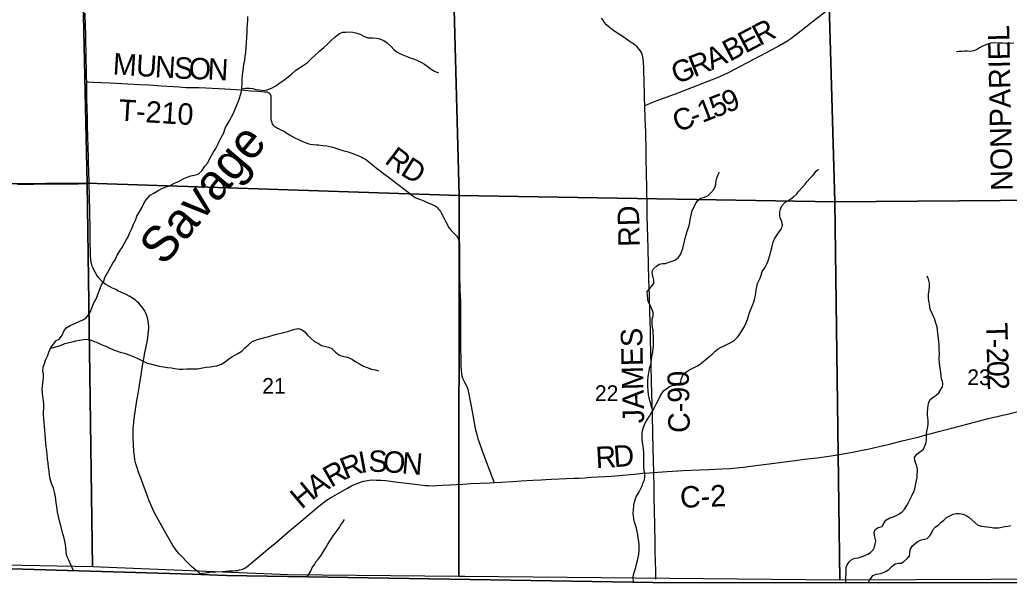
# Model space of a CAD drawing. Extents: x 1985906 to 2360102, y 891258 to 1222054.
# Drawn here: x 2119481 to 2133334, y 971932 to 979818 of the extents above; entities that cross this region are included whole.
import ezdxf

# ---------------------------------------------------------------- set-up
doc = ezdxf.new("R2010")
doc.units = 0
for name, color, linetype in [('GM_X_Adjacent_County', 7, 'Continuous'), ('GM_X_County', 7, 'Continuous'), ('GM_X_County_Road', 7, 'Continuous'), ('GM_X_County_Road_Text', 7, 'Continuous'), ('GM_X_Minor_River', 7, 'Continuous'), ('GM_X_Minor_River_Text', 7, 'Continuous'), ('GM_X_Section', 7, 'Continuous'), ('GM_X_Section_Text', 7, 'Continuous'), ('GM_X_State_Route', 7, 'Continuous'), ('GM_X_Township', 7, 'Continuous'), ('GM_X_Township_Road', 7, 'Continuous'), ('GM_X_Township_Road_Text', 7, 'Continuous')]:
    doc.layers.add(name, color=color, linetype=linetype)

msp = doc.modelspace()

# ---------------------------------------------------------------- linework, layer by layer
at = {"layer": 'GM_X_Adjacent_County'}
msp.add_lwpolyline([(2092530, 972203), (2095843, 972202), (2097718, 972193), (2100221, 972181), (2101119, 972173), (2101924, 972165), (2105883, 972151), (2108565, 972150), (2109260, 972143), (2113052, 972101), (2115190, 972104), (2119200, 972136), (2121896, 972057), (2122376, 972042), (2128345, 971944), (2133617, 971935)], dxfattribs=at)
at = {"layer": 'GM_X_County'}
msp.add_lwpolyline([(2133617, 971935), (2128345, 971944), (2122376, 972042), (2121896, 972057), (2119200, 972136), (2115190, 972104), (2113052, 972101), (2109260, 972143), (2108565, 972150), (2105883, 972151), (2101924, 972165), (2101119, 972173), (2100221, 972181), (2097718, 972193), (2095843, 972202), (2092530, 972203)], dxfattribs=at)
at = {"layer": 'GM_X_County_Road'}
for points in [[(2128232, 978618), (2128268, 978633), (2128313, 978652), (2128405, 978688), (2128697, 978797), (2129080, 978944), (2129248, 979011), (2129323, 979044), (2129412, 979087), (2129573, 979169), (2129660, 979215), (2130022, 979408), (2130109, 979454), (2130166, 979486), (2130222, 979521), (2130276, 979558), (2130355, 979618), (2130484, 979719), (2130639, 979841), (2130757, 979929), (2130784, 979947), (2130812, 979962), (2130827, 979968)], [(2128232, 978618), (2128229, 978712), (2128227, 978794), (2128221, 978926), (2128216, 979138), (2128212, 979236), (2128209, 979268), (2128204, 979300), (2128196, 979331), (2128190, 979346), (2128184, 979361), (2128176, 979375), (2128168, 979388), (2128149, 979414), (2128127, 979438), (2128102, 979459), (2128076, 979478), (2128056, 979493), (2128028, 979512), (2127994, 979535), (2127914, 979589), (2127842, 979636), (2127781, 979676), (2127733, 979714), (2127697, 979748), (2127662, 979787), (2127642, 979816), (2127626, 979840)], [(2128310, 975476), (2128301, 975726), (2128296, 975956), (2128293, 976071), (2128289, 976174), (2128282, 976389), (2128278, 976616), (2128275, 976776), (2128267, 977071), (2128264, 977203), (2128259, 977456), (2128255, 977680), (2128253, 977859), (2128250, 978055), (2128247, 978155), (2128245, 978252), (2128238, 978433), (2128232, 978614), (2128232, 978618)], [(2128358, 973483), (2128355, 973640), (2128344, 974017), (2128338, 974295), (2128331, 974590), (2128326, 974755), (2128321, 974978), (2128313, 975343), (2128310, 975476)], [(2128358, 973483), (2128412, 973487), (2128543, 973495), (2128771, 973509), (2128999, 973521), (2129130, 973525), (2129310, 973531), (2129424, 973538), (2129522, 973547), (2129652, 973562), (2129750, 973574), (2130010, 973608), (2130157, 973626), (2130335, 973651), (2130465, 973668), (2130645, 973689), (2130775, 973705), (2130840, 973715), (2130953, 973734), (2131066, 973753), (2131163, 973771), (2131275, 973792), (2131355, 973809), (2131515, 973846), (2131659, 973880), (2131834, 973923), (2131977, 973958), (2132072, 973982), (2132199, 974016), (2132262, 974033), (2132342, 974054), (2132532, 974104), (2132738, 974158), (2132865, 974191), (2133039, 974236), (2133182, 974271), (2133326, 974305), (2133533, 974352)], [(2126118, 973342), (2126222, 973347), (2126386, 973357), (2126501, 973364), (2126665, 973373), (2126779, 973379), (2126845, 973383), (2126926, 973387), (2127135, 973397), (2127243, 973402), (2127309, 973402), (2127391, 973408), (2127481, 973414), (2127677, 973426), (2127759, 973432), (2127873, 973441), (2128085, 973459), (2128199, 973470), (2128297, 973478), (2128358, 973483)], [(2128387, 971990), (2128385, 972085), (2128382, 972248), (2128379, 972363), (2128376, 972543), (2128373, 972691), (2128371, 972789), (2128368, 972903), (2128367, 972952), (2128364, 973116), (2128362, 973280), (2128358, 973476), (2128358, 973483)], [(2122004, 972070), (2122078, 972079), (2122142, 972085), (2122227, 972092), (2122315, 972097), (2122408, 972103), (2122471, 972106), (2122508, 972109), (2122533, 972112), (2122557, 972117), (2122599, 972129), (2122630, 972143), (2122665, 972165), (2122712, 972203), (2122749, 972234), (2122861, 972329), (2122982, 972430), (2123047, 972484), (2123258, 972664), (2123422, 972802), (2123670, 973011), (2123724, 973054), (2123774, 973092), (2123830, 973128), (2123929, 973184), (2124071, 973264), (2124126, 973294), (2124177, 973317), (2124218, 973334), (2124251, 973346), (2124291, 973358), (2124328, 973367), (2124374, 973374), (2124424, 973377), (2124476, 973376), (2124542, 973374), (2124607, 973369), (2124769, 973348), (2124901, 973332), (2125015, 973318), (2125155, 973301), (2125205, 973298), (2125259, 973297), (2125321, 973299), (2125393, 973303), (2125495, 973308), (2125684, 973319), (2125798, 973326), (2125927, 973332), (2126060, 973339), (2126118, 973342)]]:
    msp.add_lwpolyline(points, dxfattribs=at)
at = {"layer": 'GM_X_Minor_River'}
for points in [[(2121575, 977496), (2121655, 977536), (2121701, 977554), (2121780, 977596), (2121826, 977614), (2121878, 977634), (2121924, 977644), (2121980, 977656), (2122028, 977706), (2122070, 977770), (2122112, 977816), (2122138, 977868), (2122190, 977961), (2122228, 978019), (2122250, 978063), (2122272, 978115), (2122299, 978169), (2122337, 978237), (2122357, 978301), (2122387, 978358), (2122417, 978402), (2122443, 978458), (2122475, 978512), (2122493, 978558), (2122513, 978616), (2122539, 978670), (2122559, 978720), (2122573, 978767), (2122584, 978815), (2122592, 978867), (2122594, 978931), (2122596, 978989), (2122598, 979035), (2122604, 979086), (2122612, 979136), (2122620, 979200), (2122630, 979248), (2122638, 979308), (2122644, 979356), (2122652, 979437), (2122653, 979499), (2122659, 979573), (2122663, 979635), (2122665, 979707), (2122669, 979754), (2122673, 979808), (2122673, 979864)], [(2122590, 978853), (2122642, 978861), (2122696, 978861), (2122744, 978855), (2122788, 978844), (2122840, 978836), (2122884, 978830), (2122944, 978838), (2123006, 978862), (2123064, 978894), (2123124, 978934), (2123180, 978974), (2123238, 979018), (2123292, 979064), (2123342, 979108), (2123388, 979140), (2123448, 979178), (2123508, 979220), (2123565, 979275), (2123613, 979319), (2123681, 979383), (2123739, 979431), (2123791, 979477), (2123847, 979533), (2123895, 979579), (2123959, 979625), (2124003, 979645), (2124047, 979647), (2124095, 979651), (2124145, 979647), (2124201, 979629), (2124247, 979615), (2124299, 979588), (2124353, 979568), (2124421, 979564), (2124473, 979560), (2124519, 979550), (2124577, 979530), (2124625, 979498), (2124679, 979445), (2124719, 979401), (2124765, 979363), (2124821, 979335), (2124867, 979317), (2124913, 979300), (2124961, 979280), (2125005, 979268), (2125051, 979250), (2125097, 979226), (2125147, 979196), (2125197, 979161), (2125241, 979125), (2125285, 979097), (2125343, 979077)], [(2133400, 979489), (2133330, 979487), (2133288, 979485), (2133246, 979489), (2133198, 979493), (2133114, 979494), (2133074, 979492), (2133020, 979472), (2132958, 979450), (2132918, 979426), (2132874, 979400), (2132832, 979384), (2132790, 979374), (2132746, 979378), (2132710, 979380), (2132672, 979376), (2132634, 979374), (2132594, 979370)], [(2129808, 976126), (2129846, 976202), (2129862, 976242), (2129877, 976296), (2129913, 976348), (2129941, 976403), (2129959, 976443), (2129975, 976489), (2129987, 976539), (2129997, 976575), (2130009, 976625), (2130019, 976667), (2130031, 976707), (2130049, 976752), (2130085, 976808), (2130115, 976852), (2130147, 976892), (2130160, 976948), (2130148, 976994), (2130126, 977044), (2130124, 977083), (2130122, 977129), (2130130, 977169), (2130150, 977215), (2130192, 977259), (2130232, 977285), (2130274, 977311), (2130318, 977343), (2130358, 977383), (2130390, 977419), (2130436, 977471), (2130476, 977517), (2130503, 977557), (2130543, 977596), (2130583, 977640), (2130629, 977698), (2130665, 977726)], [(2128345, 974354), (2128325, 974399), (2128315, 974445), (2128303, 974487), (2128293, 974531), (2128284, 974571), (2128278, 974628), (2128272, 974686), (2128272, 974772), (2128280, 974816), (2128284, 974856), (2128292, 974896), (2128298, 974941), (2128314, 974989), (2128322, 975025), (2128326, 975063), (2128336, 975129), (2128344, 975171), (2128350, 975213), (2128353, 975251), (2128355, 975294), (2128355, 975380), (2128349, 975434), (2128347, 975476), (2128341, 975514), (2128337, 975552), (2128337, 975589), (2128335, 975631), (2128347, 975675), (2128349, 975719), (2128335, 975759), (2128319, 975797), (2128297, 975839), (2128281, 975876), (2128273, 975912), (2128268, 975960), (2128266, 976014), (2128296, 976054), (2128332, 976092), (2128356, 976132), (2128358, 976172), (2128348, 976211), (2128338, 976253), (2128336, 976293), (2128352, 976333), (2128396, 976369), (2128434, 976399), (2128480, 976405), (2128520, 976409), (2128566, 976425), (2128602, 976435), (2128652, 976453), (2128700, 976487), (2128730, 976533), (2128751, 976579), (2128763, 976619), (2128773, 976657), (2128781, 976697), (2128797, 976760), (2128813, 976810), (2128823, 976860), (2128839, 976896), (2128851, 976938), (2128861, 976982), (2128867, 977020), (2128877, 977063), (2128885, 977107), (2128897, 977151), (2128919, 977191), (2128942, 977241), (2128974, 977287), (2129010, 977321), (2129052, 977333), (2129112, 977355), (2129154, 977395), (2129198, 977443), (2129216, 977483), (2129226, 977519), (2129230, 977566), (2129242, 977602), (2129258, 977654), (2129278, 977690)], [(2119985, 973104), (2119977, 973163), (2119965, 973207), (2119951, 973263), (2119925, 973329), (2119905, 973394), (2119899, 973442), (2119893, 973500), (2119885, 973554), (2119877, 973610), (2119869, 973671), (2119863, 973729), (2119860, 973785), (2119852, 973843), (2119846, 973897), (2119842, 973950), (2119838, 974016), (2119832, 974074), (2119828, 974124), (2119822, 974180), (2119814, 974289), (2119812, 974333), (2119816, 974379), (2119818, 974437), (2119813, 974489), (2119805, 974544), (2119797, 974592), (2119795, 974644), (2119799, 974694), (2119807, 974766), (2119811, 974810), (2119811, 974856), (2119803, 974901), (2119807, 974955), (2119825, 975001), (2119843, 975055), (2119867, 975109), (2119890, 975167), (2119918, 975230), (2119956, 975282), (2119988, 975326), (2120036, 975352), (2120076, 975402), (2120100, 975458), (2120132, 975508), (2120188, 975540), (2120260, 975572), (2120314, 975594), (2120366, 975620), (2120410, 975648), (2120452, 975698), (2120475, 975746), (2120493, 975796), (2120515, 975846), (2120551, 975913), (2120571, 975959), (2120601, 976047), (2120627, 976107), (2120657, 976161), (2120673, 976213), (2120709, 976278), (2120739, 976326), (2120782, 976410), (2120816, 976460), (2120844, 976524), (2120880, 976584), (2120914, 976632), (2120946, 976693), (2120974, 976741), (2121002, 976791), (2121020, 976839), (2121050, 976895), (2121078, 976967), (2121107, 977025), (2121121, 977069), (2121149, 977114), (2121195, 977194), (2121223, 977254), (2121249, 977298), (2121305, 977362), (2121359, 977390), (2121427, 977434), (2121471, 977456), (2121529, 977478), (2121575, 977496)], [(2131447, 972435), (2131448, 972437), (2131456, 972483), (2131464, 972521), (2131458, 972562), (2131448, 972600), (2131444, 972642), (2131458, 972684), (2131500, 972710), (2131554, 972726), (2131584, 972778), (2131606, 972814), (2131654, 972842), (2131694, 972856), (2131734, 972868), (2131780, 972892), (2131828, 972926), (2131867, 972970), (2131901, 973020), (2131923, 973062), (2131947, 973109), (2131969, 973155), (2131997, 973215), (2132013, 973253), (2132025, 973329), (2132035, 973371), (2132043, 973413), (2132045, 973449), (2132049, 973498), (2132051, 973534), (2132041, 973572), (2132024, 973608), (2132012, 973648), (2132008, 973690), (2132038, 973736), (2132078, 973766), (2132132, 973808), (2132152, 973853), (2132168, 973889), (2132174, 973927), (2132176, 973973), (2132174, 974027), (2132186, 974081), (2132196, 974123), (2132200, 974162), (2132198, 974206), (2132192, 974250), (2132189, 974290), (2132191, 974328), (2132195, 974376), (2132199, 974422), (2132209, 974460), (2132227, 974505), (2132267, 974535), (2132311, 974565), (2132347, 974597), (2132377, 974645), (2132399, 974681), (2132405, 974717), (2132399, 974755), (2132387, 974791), (2132381, 974831), (2132375, 974880), (2132370, 974920), (2132364, 974968), (2132358, 975014), (2132354, 975084), (2132356, 975146), (2132354, 975203), (2132352, 975273), (2132350, 975309), (2132344, 975363), (2132336, 975425), (2132328, 975478), (2132324, 975520), (2132308, 975570), (2132288, 975638), (2132267, 975674), (2132251, 975723), (2132227, 975763), (2132217, 975841), (2132209, 975879), (2132203, 975929), (2132205, 975981), (2132211, 976030), (2132217, 976090), (2132219, 976134), (2132203, 976188)], [(2132203, 976188), (2132187, 976228)], [(2128086, 973064), (2128095, 973097), (2128113, 973139), (2128138, 973189), (2128164, 973231), (2128182, 973269), (2128198, 973305), (2128210, 973341), (2128226, 973380), (2128232, 973420), (2128232, 973458), (2128222, 973510), (2128216, 973558), (2128216, 973632), (2128218, 973671), (2128218, 973725), (2128216, 973761), (2128214, 973811), (2128208, 973851), (2128201, 973903), (2128197, 973943), (2128193, 974024), (2128201, 974070), (2128217, 974132), (2128235, 974172), (2128271, 974228), (2128299, 974272), (2128321, 974310), (2128343, 974351), (2128371, 974403), (2128395, 974449), (2128423, 974501), (2128440, 974541), (2128470, 974589), (2128498, 974627), (2128536, 974653), (2128576, 974683), (2128620, 974697), (2128660, 974703), (2128696, 974713), (2128738, 974747), (2128742, 974783), (2128754, 974825), (2128780, 974861), (2128822, 974894), (2128858, 974918), (2128912, 974946), (2128968, 974974), (2129006, 974996), (2129044, 975030), (2129091, 975066), (2129129, 975100), (2129177, 975140), (2129213, 975174), (2129259, 975212), (2129299, 975238), (2129335, 975250), (2129381, 975272), (2129437, 975300), (2129479, 975326), (2129529, 975378), (2129561, 975416), (2129591, 975464), (2129621, 975518), (2129647, 975566), (2129670, 975622), (2129686, 975687), (2129706, 975743), (2129726, 975787), (2129744, 975833), (2129760, 975871), (2129774, 975921), (2129782, 975959), (2129786, 975996), (2129790, 976036), (2129798, 976082), (2129808, 976126)], [(2119916, 975224), (2120006, 975247), (2120060, 975265), (2120112, 975287), (2120216, 975311), (2120268, 975325), (2120316, 975335), (2120372, 975345), (2120422, 975347), (2120482, 975335), (2120526, 975315), (2120574, 975295), (2120642, 975264), (2120688, 975248), (2120740, 975222), (2120792, 975200), (2120888, 975168), (2120944, 975154), (2121000, 975131), (2121046, 975115), (2121090, 975095), (2121136, 975075), (2121210, 975039), (2121266, 975013), (2121312, 975002), (2121432, 974972), (2121492, 974960), (2121548, 974952), (2121606, 974948), (2121650, 974938), (2121712, 974930), (2121762, 974927), (2121820, 974933), (2121878, 974933), (2121924, 974931), (2121970, 974931), (2122038, 974945), (2122090, 974955), (2122152, 974961), (2122196, 974969), (2122240, 974975), (2122304, 974997), (2122356, 975029), (2122410, 975071), (2122460, 975107), (2122532, 975149), (2122590, 975181), (2122633, 975227), (2122677, 975265), (2122735, 975313), (2122807, 975341), (2122859, 975355), (2122909, 975373), (2122967, 975387), (2123027, 975405), (2123077, 975419), (2123135, 975431), (2123191, 975445), (2123235, 975457), (2123285, 975473), (2123331, 975487), (2123377, 975497), (2123423, 975482), (2123473, 975450), (2123511, 975406), (2123557, 975362), (2123605, 975316), (2123661, 975287), (2123707, 975259), (2123761, 975245), (2123807, 975237), (2123851, 975215), (2123899, 975167), (2123949, 975130), (2123993, 975112), (2124045, 975102), (2124093, 975086), (2124137, 975064), (2124187, 975032), (2124237, 975004), (2124293, 974969), (2124345, 974951), (2124405, 974927), (2124459, 974919), (2124503, 974905)], [(2120234, 972107), (2120169, 972254), (2120142, 972310), (2120132, 972376), (2120126, 972426), (2120122, 972474), (2120110, 972519), (2120098, 972581), (2120084, 972625), (2120068, 972681), (2120056, 972739), (2120042, 972785), (2120022, 972864), (2120010, 972928), (2119999, 973004), (2119989, 973056), (2119985, 973101), (2119985, 973104)], [(2128072, 971948), (2128068, 972019), (2128078, 972066), (2128090, 972108), (2128104, 972152), (2128114, 972200), (2128128, 972250), (2128138, 972292), (2128146, 972340), (2128152, 972395), (2128154, 972435), (2128154, 972473), (2128149, 972517), (2128141, 972563), (2128133, 972615), (2128125, 972657), (2128115, 972700), (2128101, 972742), (2128087, 972786), (2128079, 972828), (2128073, 972876), (2128071, 972912), (2128073, 972960), (2128077, 973013), (2128085, 973059), (2128086, 973064)], [(2131941, 972343), (2131942, 972352), (2131948, 972404), (2131978, 972454), (2132016, 972490), (2132060, 972520), (2132104, 972538), (2132148, 972548), (2132184, 972558), (2132222, 972594), (2132244, 972634), (2132266, 972677), (2132302, 972719), (2132338, 972745), (2132380, 972785), (2132417, 972815), (2132457, 972851), (2132513, 972881), (2132549, 972899), (2132589, 972909), (2132633, 972909), (2132687, 972897), (2132729, 972880), (2132769, 972854), (2132811, 972820), (2132851, 972780), (2132895, 972744), (2132945, 972728), (2132985, 972726), (2133023, 972721), (2133071, 972715), (2133119, 972709), (2133183, 972709), (2133231, 972717), (2133271, 972725), (2133313, 972731), (2133357, 972739)], [(2123777, 972448), (2123793, 972478), (2123819, 972516), (2123843, 972556), (2123869, 972594), (2123897, 972630), (2123927, 972673), (2123953, 972709), (2123977, 972747), (2124004, 972787), (2124026, 972823)], [(2123503, 972021), (2123554, 972101), (2123574, 972154), (2123607, 972190), (2123627, 972232), (2123661, 972272), (2123697, 972316), (2123719, 972352), (2123747, 972398), (2123771, 972436), (2123777, 972448)], [(2131045, 971932), (2131049, 972151), (2131065, 972189), (2131095, 972231), (2131137, 972267), (2131177, 972281), (2131221, 972287), (2131275, 972305), (2131313, 972321), (2131353, 972337), (2131392, 972361), (2131430, 972399), (2131447, 972435)], [(2131361, 971932), (2131371, 971968), (2131401, 972004), (2131423, 972040), (2131471, 972058), (2131515, 972064), (2131551, 972074), (2131613, 972102), (2131649, 972126), (2131695, 972170), (2131735, 972202), (2131785, 972214), (2131823, 972212), (2131859, 972234), (2131906, 972276), (2131936, 972314), (2131941, 972343)]]:
    msp.add_lwpolyline(points, dxfattribs=at)
at = {"layer": 'GM_X_Section'}
for points in [[(2120308, 982876), (2120424, 977532), (2115159, 977489), (2115107, 980441), (2114959, 982915)], [(2125486, 982743), (2125632, 977359), (2120424, 977532), (2120308, 982876)], [(2130740, 982641), (2130891, 977269), (2125632, 977359), (2125486, 982743)], [(2130740, 982641), (2136011, 982694), (2136108, 977310), (2130891, 977269)], [(2115159, 977489), (2120424, 977532), (2120499, 972162), (2118029, 972207), (2115261, 972148)], [(2120424, 977532), (2125632, 977359), (2125629, 972027), (2123240, 972048), (2120499, 972162)], [(2125632, 977359), (2130891, 977269), (2130964, 971975), (2125711, 972026), (2125629, 972027)], [(2130891, 977269), (2136108, 977310), (2136196, 974765), (2136255, 971997), (2130964, 971975)]]:
    msp.add_lwpolyline(points, close=True, dxfattribs=at)
at = {"layer": 'GM_X_State_Route'}
msp.add_lwpolyline([(2122004, 972070), (2121972, 972094), (2121950, 972112), (2121887, 972166), (2121858, 972194), (2121810, 972240), (2121753, 972299), (2121714, 972341), (2121680, 972381), (2121650, 972422), (2121625, 972459), (2121581, 972536), (2121509, 972665), (2121395, 972864), (2121358, 972937), (2121324, 973011), (2121293, 973087), (2121263, 973163), (2121214, 973301), (2121184, 973380), (2121149, 973471), (2121124, 973545), (2121106, 973605), (2121093, 973661), (2121086, 973709), (2121079, 973775), (2121072, 973873), (2121067, 973966), (2121068, 974017), (2121068, 974058), (2121069, 974103), (2121072, 974127), (2121077, 974190), (2121088, 974269), (2121112, 974424), (2121121, 974491), (2121129, 974535), (2121138, 974588), (2121152, 974669), (2121161, 974735), (2121175, 974816), (2121196, 974945), (2121234, 975156), (2121268, 975332), (2121280, 975413), (2121285, 975463), (2121287, 975496), (2121287, 975529), (2121284, 975562), (2121280, 975595), (2121273, 975627), (2121264, 975659), (2121253, 975690), (2121240, 975721), (2121225, 975750), (2121207, 975778), (2121187, 975805), (2121166, 975830), (2121147, 975852), (2121122, 975877), (2121096, 975897), (2121059, 975923), (2121014, 975950), (2120971, 975972), (2120898, 976006), (2120864, 976022), (2120824, 976041), (2120779, 976063), (2120745, 976081), (2120717, 976095), (2120687, 976114), (2120655, 976138), (2120621, 976169), (2120583, 976211), (2120558, 976242), (2120540, 976275), (2120521, 976309), (2120507, 976340), (2120496, 976372), (2120485, 976408), (2120477, 976456), (2120472, 976524), (2120469, 976596), (2120466, 976672), (2120466, 976816), (2120466, 976876), (2120465, 976955), (2120462, 977055), (2120461, 977166), (2120458, 977322), (2120453, 977532), (2120453, 977536), (2120447, 977699), (2120443, 977831), (2120441, 977897), (2120437, 978028), (2120432, 978192), (2120430, 978323), (2120428, 978454), (2120424, 978585), (2120422, 978717), (2120420, 978831), (2120418, 978953), (2120417, 979012), (2120414, 979127), (2120412, 979258), (2120410, 979372), (2120408, 979503), (2120405, 979635), (2120403, 979717), (2120398, 979913)], dxfattribs=at)
at = {"layer": 'GM_X_Township'}
msp.add_lwpolyline([(2133617, 971935), (2128345, 971944), (2122376, 972042), (2121896, 972057), (2119200, 972136), (2115190, 972104), (2113052, 972101), (2109260, 972143), (2108565, 972150)], dxfattribs=at)
at = {"layer": 'GM_X_Township_Road'}
for points in [[(2120418, 978953), (2120434, 978952), (2120515, 978947), (2120621, 978940), (2120747, 978934), (2120992, 978922), (2121156, 978914), (2121286, 978906), (2121466, 978896), (2121630, 978886), (2121712, 978879), (2121761, 978874), (2121810, 978871), (2121989, 978869), (2122088, 978866), (2122268, 978857), (2122514, 978842), (2122628, 978833), (2122726, 978825), (2122824, 978818), (2122906, 978812), (2122939, 978808), (2122955, 978803), (2122970, 978795), (2122983, 978784), (2122991, 978769), (2122996, 978753), (2122997, 978736), (2122996, 978604), (2122996, 978523), (2122997, 978441), (2122998, 978424), (2123000, 978408), (2123003, 978393), (2123008, 978378), (2123015, 978363), (2123024, 978350), (2123035, 978338), (2123046, 978327), (2123059, 978318), (2123088, 978302), (2123147, 978275), (2123176, 978259), (2123259, 978210), (2123332, 978168), (2123391, 978139), (2123432, 978119), (2123451, 978111), (2123478, 978100), (2123500, 978092), (2123528, 978084), (2123553, 978079), (2123588, 978074), (2123635, 978069), (2123661, 978067), (2123722, 978061), (2123780, 978052), (2123821, 978043), (2123859, 978034), (2123904, 978022), (2123936, 978012), (2124006, 977991), (2124079, 977968), (2124166, 977937), (2124235, 977911), (2124260, 977900), (2124286, 977888), (2124311, 977872), (2124338, 977853), (2124420, 977786), (2124443, 977769), (2124477, 977742), (2124510, 977716), (2124545, 977690), (2124574, 977667), (2124640, 977620), (2124743, 977540), (2124816, 977485), (2124942, 977387), (2124988, 977351), (2125017, 977333), (2125050, 977319), (2125090, 977302), (2125138, 977283), (2125200, 977255), (2125254, 977232), (2125295, 977213), (2125310, 977203), (2125330, 977188), (2125345, 977169), (2125358, 977154), (2125370, 977135), (2125381, 977116), (2125398, 977085), (2125411, 977057), (2125430, 977019), (2125450, 976979), (2125467, 976947), (2125476, 976928), (2125487, 976910), (2125497, 976897), (2125506, 976886), (2125522, 976869), (2125577, 976814), (2125598, 976788), (2125607, 976775), (2125615, 976760), (2125622, 976745), (2125628, 976730), (2125632, 976714), (2125635, 976698), (2125637, 976682), (2125637, 976649), (2125638, 976585), (2125639, 976511), (2125638, 976425), (2125639, 976257), (2125639, 976192), (2125642, 976094), (2125644, 976027), (2125648, 975941), (2125650, 975893), (2125651, 975854), (2125651, 975826), (2125650, 975805), (2125650, 975734), (2125650, 975644), (2125649, 975554), (2125651, 975407), (2125652, 975308), (2125656, 974981), (2125659, 974915), (2125664, 974867), (2125670, 974835), (2125679, 974804), (2125692, 974774), (2125708, 974745), (2125732, 974702), (2125739, 974687), (2125745, 974672), (2125755, 974641), (2125770, 974577), (2125789, 974480), (2125822, 974287), (2125849, 974142), (2125862, 974078), (2125878, 974014), (2125896, 973951), (2125917, 973890), (2125957, 973783), (2126030, 973585), (2126053, 973524), (2126070, 973479), (2126087, 973434), (2126098, 973403), (2126108, 973372), (2126118, 973342)], [(2119450, 977518), (2119614, 977518), (2119679, 977519), (2119777, 977520), (2119875, 977521), (2119957, 977522), (2120120, 977523), (2120250, 977524), (2120299, 977524), (2120348, 977525), (2120380, 977525), (2120402, 977526), (2120415, 977528), (2120428, 977530), (2120442, 977534), (2120453, 977536)]]:
    msp.add_lwpolyline(points, dxfattribs=at)

# ---------------------------------------------------------------- texts
at = {"layer": 'GM_X_County_Road_Text'}
for s, rotation, p in [('R', 27.8917, (2129839, 979448)), ('E', 27.8922, (2129640, 979343)), ('B', 27.6645, (2129421, 979228)), ('A', 24.861, (2129167, 979110)), ('G', 21.3546, (2128674, 978915)), ('R', 21.7732, (2128922, 979012)), ('9', 21.9264, (2129384, 978509)), ('1', 21.1785, (2129036, 978373)), ('5', 21.3504, (2129209, 978440)), ('C', 21.1234, (2128691, 978240)), ('-', 21.1352, (2128921, 978328)), ('RD', 91.4581, (2128163, 976644)), ('JAMES', 91.3012, (2128224, 974172)), ('C-90', 91.0353, (2128863, 974038)), ('R', 3.122, (2127550, 973541)), ('D', 4.5264, (2127804, 973555)), ('R', 21.7768, (2124042, 973383)), ('I', 10.5185, (2124255, 973470)), ('S', 359.5819, (2124361, 973491)), ('O', 355.5604, (2124558, 973490)), ('N', 355.1474, (2124821, 973470)), ('R', 29.7976, (2123838, 973265)), ('A', 33.2349, (2123621, 973123)), ('H', 39.9254, (2123426, 972959)), ('C-2', 2.187, (2128730, 972986))]:
    msp.add_text(s, height=300, rotation=rotation, dxfattribs=at).set_placement(p)
at = {"layer": 'GM_X_Minor_River_Text'}
msp.add_text('Savage', height=500.1, rotation=49.9058, dxfattribs=at).set_placement((2121497, 976359))
at = {"layer": 'GM_X_Section_Text'}
for s, p in [('21', (2122875, 974583)), ('23', (2132747, 974704)), ('22', (2127533, 974481))]:
    msp.add_text(s, height=221, rotation=0, dxfattribs=at).set_placement(p)
at = {"layer": 'GM_X_Township_Road_Text'}
for s, rotation, p in [('NONPARIEL', 91.2073, (2133381, 977428)), ('M', 356.3631, (2120777, 979055)), ('U', 356.3639, (2121102, 979034)), ('N', 356.3866, (2121366, 979017)), ('S', 356.9841, (2121633, 979000)), ('O', 358.5174, (2121844, 978989)), ('N', 357.079, (2122105, 978983)), ('T-210', 356.4527, (2120857, 978408)), ('R', 322.7999, (2124575, 977823)), ('D', 328.3509, (2124797, 977657)), ('T', 271.4744, (2133009, 975574)), ('-', 271.4759, (2133015, 975350)), ('2', 271.507, (2133018, 975227)), ('0', 271.6134, (2133023, 975041)), ('2', 272.0528, (2133028, 974854))]:
    msp.add_text(s, height=300, rotation=rotation, dxfattribs=at).set_placement(p)

doc.saveas('drawing.dxf')
